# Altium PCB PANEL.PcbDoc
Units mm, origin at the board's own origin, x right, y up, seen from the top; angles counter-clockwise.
Board outline 80 x 36 mm, 2 copper layers (Top Layer, Bottom Layer), stack 1.071 mm thick; 72 components, 67 nets, 249 pads, 5 vias.
Unrouted connection lines stored in the file: 63.
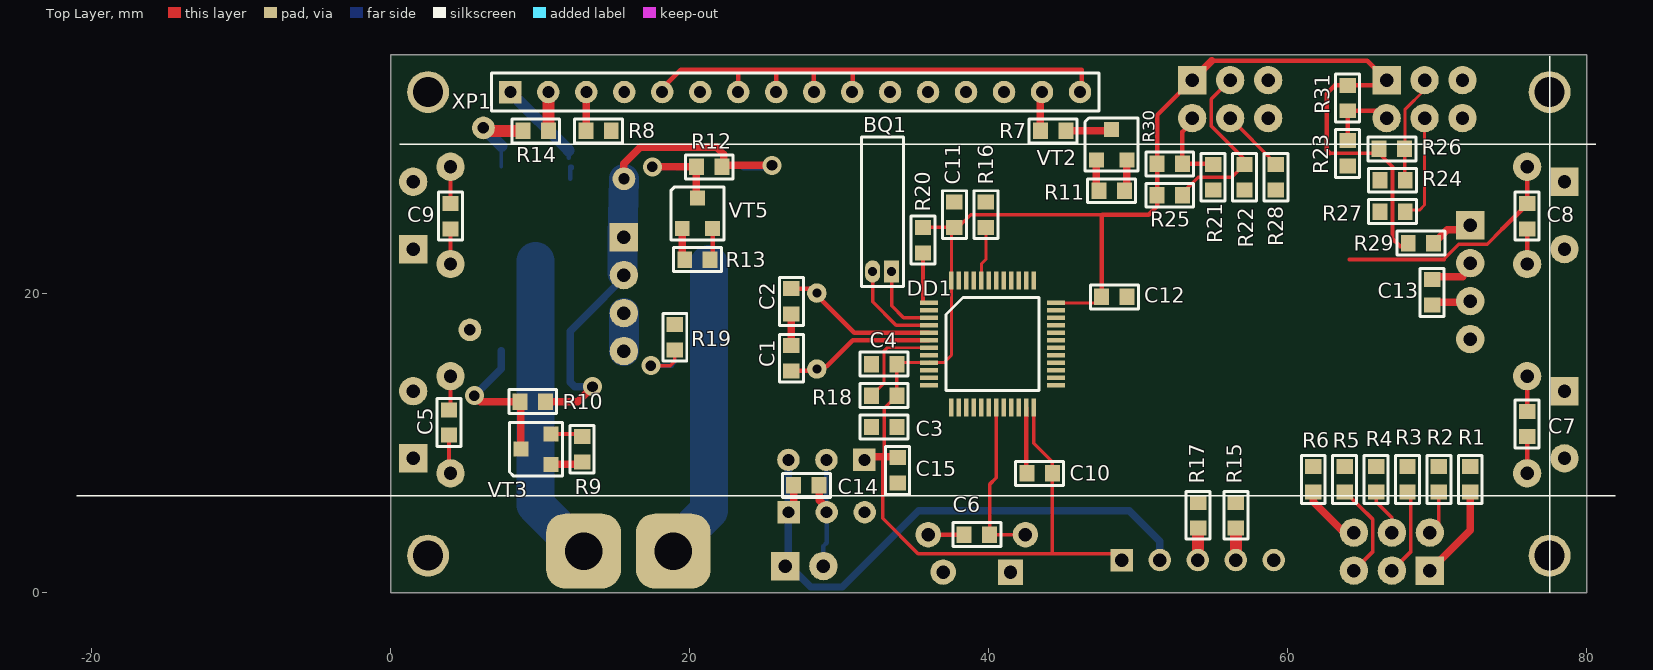
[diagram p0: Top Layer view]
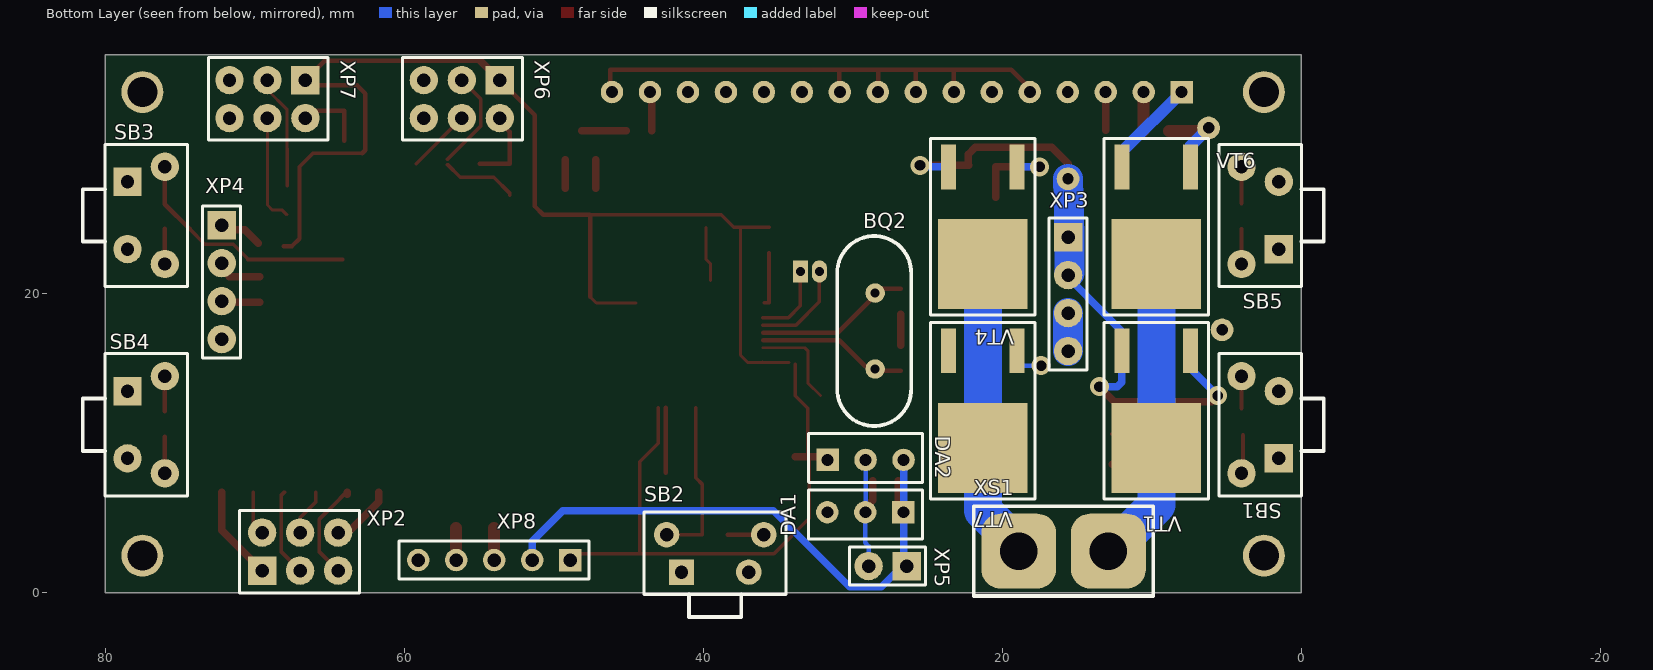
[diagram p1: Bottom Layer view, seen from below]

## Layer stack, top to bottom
Top Layer: signal copper 0.0356
Dielectric: core 1, FR-4, Dk 4.8
Bottom Layer: signal copper 0.0356

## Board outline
0,0 0,36 80,36 80,0

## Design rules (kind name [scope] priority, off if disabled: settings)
Clearance [All] p1: gap=0.2
HoleSize HoleSize_1 [All] p1: absolutevalues=TRUE maxlimit=4 minlimit=0.025 maxpercent=80.000 minpercent=20.000
HoleSize [All] p2: absolutevalues=TRUE maxlimit=2.54 minlimit=0.025 maxpercent=80.000 minpercent=20.000
PolygonConnect PolygonConnect_isVia [isVia] p1: connectstyle=Direct reliefconductorwidth=0.254 reliefentries=4 polygonreliefangle="90 Angle" airgapwidth=0.254
PolygonConnect [All] p2: connectstyle=Relief reliefconductorwidth=0.254 reliefentries=4 polygonreliefangle="90 Angle" airgapwidth=0.254
RoomDefinition PANEL [InComponentClass('PANEL')] p1: confinementstyle=ConfineIn formatcopy=TRUE lockcomponents=FALSE outline -8,-11.23 115.7,-11.23 115.7,50.6 -8,50.6
RoutingVias [All] p1: holewidth=0.711 width=1.27 viastyle="Through Hole" minholewidth=0.2 minwidth=0.6 maxholewidth=0.711 maxwidth=1.27
SilkToSilkClearance SilkToSilkClearance_1 [All] p1: silktosilkclearance=0
SilkToSilkClearance [All] p2: silktosilkclearance=0
SilkToSolderMaskClearance [IsPad] p1: minsilkscreentomaskgap=0 clearancetoexposedcopper=TRUE
SolderMaskExpansion [All] p1: expansion=0.1
Width Width_1 [All] p1: maxlimit=5 minlimit=0.1 preferedwidth=0.3 minimp=50.000000 maximp=50.000000 favimp=50.000000
Width [All] p2: maxlimit=5 minlimit=0.254 preferedwidth=0.254
25 further rules are at their usual default settings.

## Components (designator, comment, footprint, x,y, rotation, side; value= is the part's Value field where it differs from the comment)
BQ1 "32768" WatchQ 33.5,21.5 r270 top
BQ2 "8M" "HC 49S" 28.5,13.2 r90 bottom
C1 "20" Cap_0805 26.8,15.7 r270 top
C2 "20" Cap_0805 26.8,19.5 r90 top
C3 "0,01uF" Cap_0805 33,11.1 r180 top
C4 "0.47uF" Cap_0805 33,15.3 r0 top
C5 "0,01uF" Cap_0805 3.9,11.4 r90 top
C6 "0,01uF" Cap_0805 39.2,3.9 r180 top
C7 "0,01uF" Cap_0805 76,11.3 r270 top
C8 "0,01uF" Cap_0805 76,25.2 r270 top
C9 "0,01uF" Cap_0805 4,25.2 r90 top
C10 "0.47uF" Cap_0805 43.4,8 r0 top
C11 "0.47uF" Cap_0805 37.7,25.3 r270 top
C12 "0.47uF" Cap_0805 48.4,19.8 r180 top
C13 "100" Cap_0805 69.65,20.1 r90 top
C14 "0.47uF" Cap_0805 27.8,7.2 r180 top
C15 "0.47uF" Cap_0805 33.9,8.2 r90 top
DA1 "L78L05" kren 31.7,5.4 r90 bottom
DA2 "L78L03" kren 26.6,8.9 r270 bottom
DD1 "STM32F100C8T6B" LQFP48 36,19.4 r0 top
R1 "220" Res_0805 72.2,7.6 r90 top
R2 "220" Res_0805 70.1,7.6 r90 top
R3 "220" Res_0805 68,7.6 r90 top
R4 "220" Res_0805 65.9,7.6 r270 top
R5 "220" Res_0805 63.8,7.6 r270 top
R6 "220" Res_0805 61.7,7.6 r90 top
R7 "1k" Res_0805 44.3,30.9 r180 top
R8 "1k" Res_0805 13.9,30.91 r180 top
R9 "1k" Res_0805 12.8,9.616 r90 top
R10 "1k" Res_0805 9.5,12.8 r180 top
R11 "10k" Res_0805 48.216,26.9 r180 top
R12 "1k" Res_0805 21.3,28.5 r0 top
R13 "1k" Res_0805 20.516,22.3 r180 top
R14 "1k" Res_0805 9.7,30.9 r0 top
R15 "100" Res_0805 56.52,5.2 r90 top
R16 "10k" Res_0805 39.8,25.3 r90 top
R17 "100" Res_0805 54,5.2 r90 top
R18 "51k" Res_0805 33,13.2 r0 top
R19 "1k" Res_0805 19,17.1 r270 top
R20 "10" Res_0805 35.6,23.6 r90 top
R21 "220" Res_0805 55,27.8 r270 top
R22 "220" Res_0805 57.1,27.8 r270 top
R23 "220" Res_0805 64,29.4 r270 top
R24 "220" Res_0805 67,27.6 r180 top
R25 "10k" Res_0805 52.1,26.6 r180 top
R26 "10k" Res_0805 66.96,29.7 r180 top
R27 "1k" Res_0805 67,25.5 r180 top
R28 "1k" Res_0805 59.2,27.8 r270 top
R29 "10k" Res_0805 68.9,23.4 r180 top
R30 "10k" Res_0805 52.1,28.7 r180 top
R31 "10k" Res_0805 64,33.1 r90 top
SB1 "TS A3PV 130" "TS A3PV 130"#1 8.5,13 r90 bottom
SB2 "TS A3PV 130" "TS A3PV 130"#2 37.45,8.4 r180 bottom
SB3 "TS A3PV 130" "TS A3PV 130"#1 71.5,23.5 r270 bottom
SB4 "TS A3PV 130" "TS A3PV 130"#1 71.5,9.5 r270 bottom
SB5 "TS A3PV 130" "TS A3PV 130"#1 8.5,27 r90 bottom
VT1 "NVD5117PL" TO-252 9,9.9 r0 bottom
VT2 "IRLML9303" SOT-23 47.2,31 r0 top
VT3 "N-CHAN_SOT-23" SOT-23 8.7,8.6 r90 top
VT4 "NVD5117PL" TO-252 20.6,22.2 r0 bottom
VT5 "N-CHAN_SOT-23" SOT-23 19.5,26.4 r0 top
VT6 "2SK3919" TO-252 9,22.2 r0 bottom
VT7 "2SK3919" TO-252 20.6,9.9 r0 bottom
XP1 "DISP16_2.54" DISP16_2.54 8,33.5 r90 top
XP2 "PLD-6" CONN_2.54_6_2 69.5,1.5 r90 bottom
XP3 "SWD" CONN_2.54_4 15.6,23.8 r180 bottom
XP4 "SWD" CONN_2.54_4 72.2,24.6 r180 bottom
XP5 "CONNECT_2.54_2" CONN_2.54_2 26.4,1.8 r270 bottom
XP6 "PLD-6" CONN_2.54_6_2 53.6,34.3 r270 bottom
XP7 "PLD6" CONN_2.54_6_2 66.6,34.3 r270 bottom
XP8 "UART_CONN" CONN_2.54_5 48.9,2.2 r270 bottom
XS1 "PELTIER" PELTIER 12.9,2.8 r270 bottom

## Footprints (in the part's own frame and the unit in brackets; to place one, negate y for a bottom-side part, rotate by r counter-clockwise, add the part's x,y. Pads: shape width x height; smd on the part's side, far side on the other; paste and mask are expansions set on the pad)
Cap_0805 [mm]
  rect 1x1.1 smd: 1(-0.85,0) 2(0.85,0)
  silkscreen extent -1.6,-0.8 1.6,0.8
CONN_2.54_2 [mm]
  rect 1.9x1.9 hole 0.9: 1(0,0)
  round 1.9 hole 0.9: 2(0,-2.54)
  silkscreen extent -1.27,-3.81 1.27,1.27
CONN_2.54_4 [mm]
  rect 1.9x1.9 hole 0.9: 1(0,0)
  round 1.9 hole 0.9: 2(0,-2.54) 3(0,-5.08) 4(0,-7.62)
  silkscreen extent -1.27,-8.89 1.27,1.27
CONN_2.54_5 [mm]
  rect 1.5x1.5 hole 0.9: 1(0,0)
  round 1.5 hole 0.9: 2(0,-2.54) 3(0,-5.08) 4(0,-7.62) 5(0,-10.16)
  silkscreen extent -1.27,-11.43 1.27,1.27
CONN_2.54_6_2 [mm]
  rect 1.9x1.9 hole 0.9: 1(0,0)
  round 1.9 hole 0.9: 2(2.54,0) 3(0,-2.54) 4(2.54,-2.54) 5(0,-5.08) 6(2.54,-5.08)
  silkscreen extent -1.5,-6.5 4,1.5
DISP16_2.54 [mm]
  rect 1.5x1.5 hole 0.8: 1(0,0)
  round 1.5 hole 0.8: 2(0,-2.54) 3(0,-5.08) 4(0,-7.62) 5(0,-10.16) 6(0,-12.7) 7(0,-15.24) 8(0,-17.78) 9(0,-20.32) 10(0,-22.86) 11(0,-25.4) 12(0,-27.94) 13(0,-30.48) 14(0,-33.02) 15(0,-35.56) 16(0,-38.1)
  silkscreen extent -1.27,-39.37 1.27,1.27
"HC 49S" [mm] "DIP QUARTZ"
  round 1.3 hole 0.6: 1(1.778,0) 2(6.858,0)
  silkscreen extent -2.03,-2.41 10.67,2.54
kren [mm] "L78L05"
  rect 1.5x1.5 hole 0.8: 1(0,-5.08)
  round 1.5 hole 0.8: 2(0,-2.54) 3(0,0)
  silkscreen extent -1.78,-6.35 1.5,1.27
LQFP48 [mm]
  rect 1.2x0.3 smd: 1(0,0) 2(0,-0.5) 3(0,-1) 4(0,-1.5) 5(0,-2) 6(0,-2.5) 7(0,-3) 8(0,-3.5) 9(0,-4) 10(0,-4.5) 11(0,-5) 12(0,-5.5) 25(8.5,-5.5) 26(8.5,-5) 27(8.5,-4.5) 28(8.5,-4) 29(8.5,-3.5) 30(8.5,-3) 31(8.5,-2.5) 32(8.5,-2) 33(8.5,-1.5) 34(8.5,-1) 35(8.5,-0.5) 36(8.5,0)
  rect 0.3x1.2 smd: 13(1.5,-7) 14(2,-7) 15(2.5,-7) 16(3,-7) 17(3.5,-7) 18(4,-7) 19(4.5,-7) 20(5,-7) 21(5.5,-7) 22(6,-7) 23(6.5,-7) 24(7,-7) 37(7,1.5) 38(6.5,1.5) 39(6,1.5) 40(5.5,1.5) 41(5,1.5) 42(4.5,1.5) 43(4,1.5) 44(3.5,1.5) 45(3,1.5) 46(2.5,1.5) 47(2,1.5) 48(1.5,1.5)
  silkscreen extent 1.13,-5.86 7.36,0.37
PELTIER [mm] "Peltier Element"
  rrect50% 5x5 hole 2.5: 1(0,0) 2(0,-6)
  silkscreen extent -3,-9 3,3
Res_0805 [mm]
  rect 1x1.1 smd: 1(-0.85,0) 2(0.85,0)
  silkscreen extent -1.6,-0.8 1.6,0.8
SOT-23 [mm]
  rect 1x1 smd: 1(0,-2.032) 2(2.032,-2.032) 3(1.016,0)
  silkscreen extent -0.76,-2.79 2.79,0.76
TO-252 [mm] "TO252"
  rect 1x3 smd: 1(-1.6,-6.3) 3(3,-6.3)
  rect 6x6 smd: 2(0.7,0.2)
  silkscreen extent -2.8,-8.2 4.2,3.6
"TS A3PV 130"#1 [mm] "Button"
  rect 1.9x1.9 hole 0.9: 1(-4,-7)
  round 1.9 hole 0.9: 2(0.5,-7) 3(-5,-4.5) 4(1.5,-4.5)
  silkscreen extent -6.5,-10 3,-3
"TS A3PV 130"#2 [mm] "Button"
  rect 1.7x1.7 hole 0.9: 1(-4,-7)
  round 1.7 hole 0.9: 2(0.5,-7) 3(-5,-4.5) 4(1.5,-4.5)
  silkscreen extent -6.5,-10 3,-3
WatchQ [mm] "Quartz"
  rect 1.5x1 hole 0.6: 1(0,0)
  oval 1.5x1 hole 0.6: 2(0,-1.27)
  silkscreen extent -9,-2 1,0.8

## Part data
BQ1: library part WatchQ
BQ2: library part "BQ_HC 49S"
C1 C2 C3 C4 C5 C6 C7 C8 C9 C10 C11 C12 C13 C14 C15: library part Cap_0805
DA1 DA2: library part kren
R1 R2 R3 R4 R5 R6 R7 R8 R9 R10 R11 R12 R13 R14 R15 R16 R17 R18 R19 R20 R21 R22 R23 R24 R25 R26 R27 R28 R29 R30 R31: library part Res_0805
SB1 SB2 SB3 SB4 SB5: "Button"
VT1 VT4: library part P-CHAN_TO-252
VT2: library part P-CHAN_SOT-23
VT6 VT7: library part N-CHAN_TO-252
XP2 XP6 XP7: library part CONNECT_2.54_6_2
XP3 XP4: library part CONNECT_SWD
XP8: library part CONNECT_2.54_5

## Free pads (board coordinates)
  round 2.8 hole 2: 0(2.5,2.5) 0(2.5,33.5) 0(77.5,2.5) 0(77.5,33.5)
  round 1.524 hole 0.762: 0(5.3,17.6) 0(6.2,31.1) 0(15.6,27.7)

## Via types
v1: diameter 1.27, hole 0.711, Top Layer to Bottom Layer, 5 vias

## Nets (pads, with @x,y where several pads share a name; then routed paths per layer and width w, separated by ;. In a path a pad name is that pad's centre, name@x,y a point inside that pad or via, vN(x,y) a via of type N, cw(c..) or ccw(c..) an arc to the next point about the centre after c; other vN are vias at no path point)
5V: R11.1 R14.2 R19.1 VT2.2 XP1.2 | length 4.5
  Top Layer w0.5: R11.1@49.232,27.066 VT2.2
  Top Layer w0.8: R14.2@10.54,30.91 XP1.2
+12V: DA1.3 pad.0@5.3,17.6 pad.0@15.6,27.7 R10.1 R12.2 VT1.3 VT4.3 XP3.1 XP3.2 | length 34.6
  Top Layer w0.5: R10.1 12.5,12.8 v1(13.5,13.8) ; pad.0@15.705,27.7 15.6,27.7 15.6,28.7 16.7,29.8 21.8,29.8 22.275,29.325 R12.2@22.275,28.625 ; R12.2@22.25,28.6 v1(25.5,28.6)
  Bottom Layer w0.5: v1@13.4,13.9 v1(13.5,13.8) 12.3,13.8 12,14.1 VT1.3 12,17.5 13.05,18.55 15.6,21.1 XP3.2 ; VT4.3 25.4,28.5 v1(25.5,28.6)
  Bottom Layer w2: XP3.2@15.5,21.4 15.5,23.9 pad.0@15.6,27.7
GND: C1.1 C2.1 C3.1 C4.1 C5.2 C6.2 C7.2 C8.2 C9.2 C10.1 C11.1 C12.1 C13.1 C14.1 C15.1 DA1.2 DA2.2 DD1.8 DD1.23 DD1.35 DD1.47 R9.2 R13.1 R16.2 SB1.4 SB2.4 SB3.4 SB4.4 SB5.4 VT3.2 VT5.2 VT6.3 VT7.3 XP1.1 XP1.5 XP1.7 XP1.8 XP1.9 XP1.10 XP1.16 XP3.3 XP3.4 XP4.3 XP5.2 XP6.6 XP7.6 XP8.5 | length 79.3
  Top Layer w0.3: C5.2@4,12.35 SB1.4 ; C9.2 SB5.4 ; VT3.2 R9.2@12.634,10.632 ; XP1.5 18.16,33.76 19.4,35 25.78,35 ; R13.1@21.532,22.466 VT5.2 ; XP1.7 23.24,34.96 ; XP1.8 25.78,35 ; XP1.9 28.29,33.53 28.29,35 ; XP1.10@30.9,33.54 30.9,35 ; SB2.4 C6.2 ; C10.1@42.5,8.05 DD1.23 ; XP1.16@46.2,33.6 46.2,35 30.9,35 ; XP4.3@71.87,19.45 XP4.3@72.2,19.12 ; SB4.4 C7.2 ; SB3.4 C8.2 ; 25.78,35 28.29,35 ; 28.29,35 30.9,35
  Top Layer w0.5: C1.1 C2.1 ; C14.1@28.65,7.5 28.65,6.21 DA1.2@29.16,5.7 ; C13.1@69.65,19.45 XP4.3@71.87,19.45
  Bottom Layer w0.3: VT6.3@11.9,29.1 VT6.3@11.9,29.6 ; VT6.3@12,27.7 VT6.3 ; VT6.3@12.1,28.4 VT6.3@12.1,28.5 ; XP5.2@28.94,2.1 28.94,3.14 29.16,3.36 DA1.2 29.14,5.42 DA2.2
  Bottom Layer w0.8: XP1.1 VT6.3@11.9,29.6
  Bottom Layer w2: XP3.4 XP3.3
NetBQ1_1: BQ1.1 DD1.3 | length 5.1
  Top Layer w0.24: BQ1.1 33.5,19.2 34.3,18.4 DD1.3
NetBQ1_2: BQ1.2 DD1.4 | length 6.5
  Top Layer w0.24: BQ1.2 32.23,19.47 33.8,17.9 DD1.4
NetBQ2_1: BQ2.1 C1.2 DD1.6 | length 9.8
  Top Layer w0.3: C1.2 BQ2.1@28.372,14.85 ; BQ2.1@28.5,15.156 29.156,15.156 30.9,16.9 DD1.6
NetBQ2_2: BQ2.2 C2.2 DD1.5 | length 10.5
  Top Layer w0.2: BQ2.2@28.24,20.35 BQ2.2@28.532,20.058
  Top Layer w0.24: BQ2.2@28.532,19.868 BQ2.2@28.532,20.058
  Top Layer w0.3: C2.2 BQ2.2@28.24,20.35 ; BQ2.2@28.532,19.868 31,17.4 DD1.5
NetC3_2: C3.2 DD1.7 R18.1 | length 6.4
  Top Layer w0.2: R18.1 33,14.05 33,16.2 33.2,16.4 DD1.7
NetC5_1: C5.1 DD1.18 SB1.3 | length 2.5
  Top Layer w0.3: SB1.3@3.9,8.1 C5.1
NetC6_1: C6.1 DD1.19 SB2.3 | length 11.1
  Top Layer w0.24: DD1.19 40.5,7.7 40.05,7.25 C6.1 SB2.3
NetC7_1: C7.1 DD1.20 SB4.3 | length 2.4
  Top Layer w0.3: C7.1 SB4.3
NetC8_1: C8.1 DD1.39 SB3.3 | length 16
  Top Layer w0.24: 64.1,22.3 70.45,22.3 70.45,22.35 71.43,23.33 73.33,23.33 74.35,24.35
  Top Layer w0.3: 74.35,24.35 76,26 C8.1 SB3.3
NetC9_1: C9.1 DD1.40 SB5.3 | length 2.4
  Top Layer w0.24: SB5.3 C9.1
NetC13_2: C13.2 DD1.37 XP4.2 | length 2.8
  Top Layer w0.2: 71.69,21.15 XP4.2@72.2,21.66
  Top Layer w0.5: C13.2@69.65,21.15 71.69,21.15
NetC14_2: C14.2 DA1.1 DA2.3 XP5.1 XP8.2 | length 38.8
  Top Layer w0.5: DA1.1@26.62,5.7 26.95,6.03 C14.2 C14.2@26.95,7.5
  Bottom Layer w0.24: XP5.1@26.4,2.1 XP5.1@26.6,2.3
  Bottom Layer w0.5: XP5.1@26.4,2.1 28.1,0.4 30.2,0.4 35.3,5.5 49.4,5.5 51.44,3.46 XP8.2 ; XP5.1@26.6,2.3 DA2.3
NetDD1_1: DD1.1 R20.1 | length 3.7
  Top Layer w0.24: R20.1 35.6,19.4 DD1.1@35.9,19.4
NetDD1_10: DD1.10 R19.2 VT7.1 | length 4.7
  Top Layer w0.24: v1(17.4,15.2) 18.7,15.2 19,15.5 R19.2
  Bottom Layer w0.24: VT7.1@18.8,15.2 19,15.4 VT7.1@19,15.9
  Bottom Layer w0.3: v1(17.4,15.2) VT7.1@18.8,15.2
NetDD1_11: DD1.11 pad.0@6.2,31.1 R14.1 VT6.1 | length 5.5
  Top Layer w0.8: pad.0@6.4,30.9 R14.1
  Bottom Layer w0.24: VT6.1 VT6.1@7.4,29.9
  Bottom Layer w0.8: pad.0@6.2,31.1 VT6.1@7.4,29.9
NetDD1_12: DD1.12 R13.2 VT5.1 | length 1.9
  Top Layer w0.5: R13.2@19.5,22.466 VT5.1
NetDD1_13: DD1.13 R9.1 VT3.1 | length 1.9
  Top Layer w0.5: VT3.1 R9.1@12.634,8.6
NetDD1_14: DD1.14 R8.1
NetDD1_15: DD1.15 R28.2
NetDD1_16: DD1.16 R27.2
NetDD1_21: DD1.21 R21.2
NetDD1_22: DD1.22 R22.2
NetDD1_25: DD1.25 XP1.11
NetDD1_26: DD1.26 XP1.12
NetDD1_27: DD1.27 XP1.13
NetDD1_28: DD1.28 XP1.14
NetDD1_30: DD1.30 R15.2
NetDD1_31: DD1.31 R17.2
NetDD1_33: DD1.33 R11.2 VT2.1 | length 1.9
  Top Layer w0.5: R11.2@47.2,27.066 VT2.1
NetDD1_34: DD1.34 XP4.4
NetDD1_42: DD1.42 R23.2
NetDD1_43: DD1.43 R24.2
NetDD1_44: DD1.44 R16.1 | length 3.7
  Top Layer w0.2: DD1.44 39.5,22 39.8,22.3 R16.1
NetDD1_45: DD1.45 XP1.4
NetDD1_46: DD1.46 XP1.6
NetR1_1: R1.1 XP2.1 | length 6.4
  Top Layer w0.5: XP2.1 72.2,4.2 R1.1
NetR2_1: R2.1 XP2.2 | length 3
  Top Layer w0.24: XP2.2 70.1,4.64 R2.1
NetR3_1: R3.1 XP2.3 | length 5.9
  Top Layer w0.24: XP2.3 68.23,2.77 68.23,6.52 R3.1
  Bottom Layer w0.24: XP2.3 XP2.3@67,1.5
NetR4_2: R4.2 XP2.4 | length 2.1
  Top Layer w0.24: R4.2 65.9,6.1 66.96,5.04
NetR5_2: R5.2 XP2.5 | length 6.8
  Top Layer w0.24: R5.2 63.85,6.75 64.78,5.82 65.69,4.91 65.69,2.77 XP2.5
  Top Layer w0.5: R5.2@63.8,6.6 R5.2
  Bottom Layer w0.24: XP2.5 XP2.5@64.42,1.52
NetR6_1: R6.1 XP2.6 | length 4.2
  Top Layer w0.5: R6.1 61.7,6.1 63.76,4.04 XP2.6
NetR7_1: R7.1 VT2.3 | length 3
  Top Layer w0.5: R7.1 VT2.3@48.116,30.9
NetR7_2: R7.2 XP1.15 | length 2.5
  Top Layer w0.5: R7.2 XP1.15@43.45,33.39
NetR8_2: R8.2 XP1.3 | length 2.6
  Top Layer w0.5: R8.2@13.08,30.94 XP1.3
NetR10_2: R10.2 VT1.1 VT3.3 | length 10.1
  Top Layer w0.5: v1(5.6,13.2) 6,12.8 R10.2 ; VT3.3 R10.2@8.7,12.75
  Bottom Layer w0.5: v1(5.6,13.2) 7.4,15 VT1.1
NetR12_1: R12.1 VT4.1 VT5.3 | length 6.5
  Top Layer w0.5: v1(17.5,28.5) R12.1 VT5.3@20.45,26.466
  Bottom Layer w0.5: v1(17.5,28.5) VT4.1
NetR15_1: R15.1 XP8.4 | length 2.2
  Top Layer w0.8: XP8.4 R15.1
NetR17_1: R17.1 XP8.3 | length 2.1
  Top Layer w0.8: XP8.3@54,2.22 R17.1
NetR21_1: R21.1 R30.1 XP6.2 | length 5.3
  Top Layer w0.24: XP6.2@53.6,31.5 XP6.2
  Top Layer w0.3: XP6.2@53.6,31.5 52.95,30.85 R30.1 R21.1@54.95,28.7
NetR22_1: R22.1 R25.1 XP6.3 | length 12.2
  Top Layer w0.24: R25.1 52.95,26.75 54,27.8 56.25,27.8 R22.1 ; XP6.3 54.87,33.03 54.87,31.23 R22.1@57.1,29
  Top Layer w0.3: XP6.3@56.14,33.94 XP6.3
NetR23_1: R23.1 R31.1 XP7.2 | length 4.1
  Top Layer w0.3: R23.1 R31.1 XP7.2@66.11,32.25
NetR24_1: R24.1 R26.1 XP7.3 | length 7.9
  Top Layer w0.2: R26.1@67.85,29.35 67.85,32.35 69.14,33.64 XP7.3
  Top Layer w0.24: R24.1@67.81,27.24 R26.1
NetR27_1: R27.1 XP7.4 | length 7.4
  Top Layer w0.2: R27.1@67.85,25.3 68.15,25.6 68.8,25.6 69.14,25.94 XP7.4
NetR28_1: R28.1 XP6.4 | length 4.3
  Top Layer w0.24: XP6.4 R28.1@59.2,28.7
NetR29_1: R29.1 XP4.1 | length 2.9
  Top Layer w0.5: R29.1 70.65,24.3 XP4.1@72.28,24.3
NetVT1_2: VT1.2 VT6.2 XS1.1 | length 20.8
  Bottom Layer w2.54: VT6.2@9.7,22.2 VT6.2 VT1.2 9.7,5.9 XS1.1@12.9,2.7
NetVT4_2: VT4.2 VT7.2 XS1.2 | length 20.2
  Bottom Layer w2.54: XS1.2@18.9,2.7 18.9,3.1 21.3,5.5 VT7.2 ; VT7.2@21.3,9.8 VT4.2
P1: DD1.17 R1.2
P2: DD1.29 R2.2
P3: DD1.32 R3.2
P4: DD1.38 R4.1
P5: DD1.2 R5.1
P6: DD1.41 R6.2
VCC: C4.2 C10.2 C11.2 C12.2 C15.2 DA2.1 DD1.9 DD1.24 DD1.36 DD1.48 R18.2 R20.2 R25.2 R26.2 R29.2 R30.2 R31.2 XP6.1 XP7.1 XP8.1 | length 118.3
  Top Layer w0.2: C4.2@34.25,15.4 DD1.9 ; DD1.9@36.05,15.45 36.1,15.4 37,15.4 37.5,15.9 DD1.48 C11.2@37.5,24.4 ; DD1.36 47.15,19.4 C12.2
  Top Layer w0.24: 32.9,9.1 32.9,5 35.27,2.63 48.47,2.63 XP8.1 ; 33,9.1 33,12.35 R18.2 C4.2 ; R20.2 C11.2 37.95,24.45 38.8,25.3 47.5,25.3 ; DD1.24 43,10.016 44.25,8.766 C10.2 44.25,2.63 ; 62.8,29.4 66.1,29.4 67,28.5 67,23.7
  Top Layer w0.3: C12.2 47.55,25.25 ; 47.6,25.3 50.7,25.3 51.25,25.85 R25.2 R30.2 51.25,31.95 XP6.1@53.15,33.85 ; 54.9,35.6 65.3,35.6 XP7.1 ; 62.8,29.4 62.6,29.6 62.6,33.4 63.15,33.95 R31.2 XP7.1@66.25,33.95 ; 67,23.7 67.5,23.2 R29.2@68.05,23.2
  Top Layer w0.5: DA2.1@31.7,9.1 32.9,9.1 ; 33,9.1 C15.2@33.85,9.1 ; XP6.1 54.9,35.6
pads on no net: SB1.1 SB1.2 SB2.1 SB2.2 SB3.1 SB3.2 SB4.1 SB4.2 SB5.1 SB5.2 XP6.5 XP7.5

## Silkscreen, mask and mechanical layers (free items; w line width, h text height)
Top Overlay:
  lines w0.1: -21,6.5 81.9,6.5 ; 0.6,30 80.6,30 ; 77.5,0 77.5,35.9
Mechanical 1:
  the board outline again, w0.1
